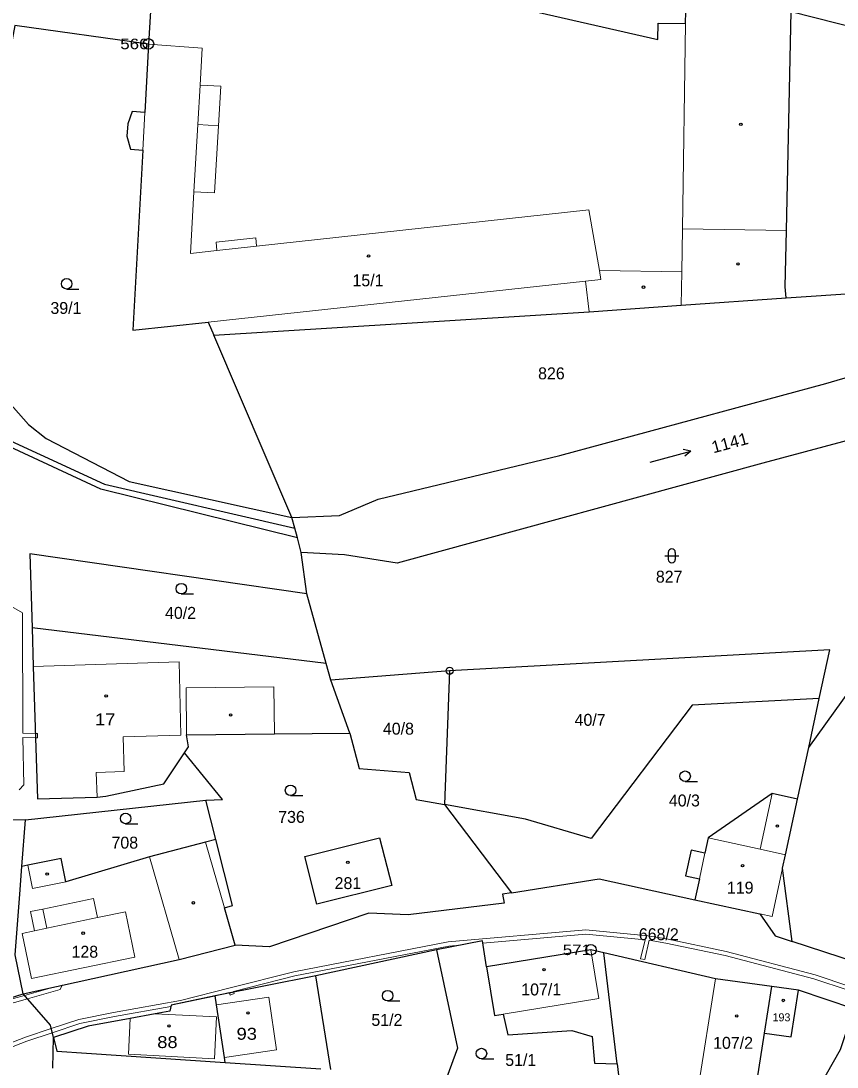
# Model space of a CAD drawing. Extents: x -758887 to -754328, y -1031688 to -1029144.
# Drawn here: x -756296.2 to -756179.9, y -1030447.4 to -1030298.3 of the extents above; entities that cross this region are included whole.
import ezdxf
from ezdxf.enums import TextEntityAlignment as Align

# ---------------------------------------------------------------- set-up
doc = ezdxf.new("R2010")
doc.units = 0
doc.header["$LTSCALE"] = 0.68
for name, color, linetype, lineweight in [('1', 7, 'Continuous', 25), ('13', 7, 'Continuous', 13), ('3', 7, 'Continuous', 25), ('4', 7, 'Continuous', 13), ('5', 7, 'Continuous', 25), ('8', 7, 'Continuous', 25)]:
    doc.layers.add(name, color=color, linetype=linetype, lineweight=lineweight)
doc.layers.add('2', color=7, linetype='Continuous')

msp = doc.modelspace()

# ---------------------------------------------------------------- linework, layer by layer
at = {"layer": '1'}
for p, q in [((-756186.43, -1030296.97), (-756172.86, -1030300.43)), ((-756187.15, -1030337.79), (-756168.3, -1030336.57)), ((-756256.83, -1030371.98), (-756257.2, -1030370.6)), ((-756252.73, -1030389.88), (-756255.47, -1030379.95)), ((-756252.73, -1030389.88), (-756294.64, -1030384.82)), ((-756252.07, -1030392.26), (-756252.73, -1030389.88)), ((-756235.12, -1030390.94), (-756252.07, -1030392.26)), ((-756249.36, -1030399.82), (-756252.07, -1030392.26)), ((-756295.58, -1030412.18), (-756269.89, -1030409.39)), ((-756268.47, -1030415), (-756269.89, -1030409.39)), ((-756235.85, -1030410), (-756226.28, -1030422.56)), ((-756177.1, -1030432.5), (-756186.27, -1030429.51)), ((-756254.19, -1030434.42), (-756268.53, -1030437.28)), ((-756252.05, -1030447.75), (-756254.19, -1030434.42)), ((-756190.23, -1030442.57), (-756189.18, -1030435.94)), ((-756185.37, -1030436.47), (-756189.18, -1030435.94)), ((-756177.49, -1030439.12), (-756185.37, -1030436.47)), ((-756268.53, -1030437.28), (-756274.82, -1030438.59)), ((-756191.78, -1030452.34), (-756190.23, -1030442.57)), ((-756291.68, -1030447.55), (-756291.6, -1030443.2)), ((-756211.22, -1030446.93), (-756210.83, -1030450.16))]:
    msp.add_line(p, q, dxfattribs=at)
for points in [[(-756277.43, -1030291.05), (-756277.68, -1030295.34), (-756278.04, -1030301.63)], [(-756277.43, -1030291.05), (-756267.6, -1030291.62), (-756262.8, -1030291.89), (-756257.46, -1030292.14), (-756257.5, -1030292.9), (-756254.89, -1030293.02), (-756248.59, -1030293.81), (-756241.94, -1030294.65), (-756222.37, -1030297.12), (-756205.42, -1030300.96), (-756205.39, -1030298.66), (-756201.49, -1030298.72), (-756201.46, -1030296.97), (-756186.43, -1030296.97)], [(-756187.15, -1030337.79), (-756187.28, -1030336.24), (-756187.11, -1030328.19), (-756186.43, -1030296.97)], [(-756278.04, -1030301.63), (-756297.11, -1030298.97), (-756305.25, -1030342.25), (-756301.61, -1030348.57), (-756295.16, -1030355.83), (-756292.62, -1030357.83), (-756280.82, -1030363.98), (-756257.6, -1030369.08), (-756268.75, -1030343.09)], [(-756278.04, -1030301.63), (-756278.58, -1030311.36), (-756280.37, -1030311.26), (-756281.01, -1030312.99), (-756281.13, -1030314.74), (-756280.62, -1030316.63), (-756278.88, -1030316.76), (-756280.3, -1030342.42), (-756269.52, -1030341.25), (-756268.75, -1030343.09)], [(-756256.83, -1030371.98), (-756284.83, -1030365.07), (-756303.39, -1030356.44), (-756320.2, -1030338.64), (-756353.07, -1030315.54), (-756371.23, -1030308.81), (-756412.68, -1030321.55), (-756420.88, -1030328.31), (-756431.02, -1030341.76)], [(-756383.9, -1030311.42), (-756371.64, -1030307.47), (-756352.7, -1030314.7), (-756319.28, -1030338.35), (-756302.7, -1030355.9), (-756284.33, -1030364.33), (-756257.2, -1030370.6), (-756257.6, -1030369.08)], [(-756268.75, -1030343.09), (-756215.21, -1030339.78), (-756202.09, -1030338.85), (-756187.15, -1030337.79)], [(-756257.6, -1030369.08), (-756250.83, -1030368.82), (-756245.31, -1030366.48), (-756219.4, -1030360.24), (-756181.47, -1030350.02), (-756152, -1030341.34)], [(-756183.93, -1030401.88), (-756175.52, -1030390.23), (-756148.24, -1030383.26), (-756132.67, -1030381.9), (-756135.32, -1030348.08)], [(-756149.65, -1030350.41), (-756190.47, -1030361.36), (-756242.58, -1030375.6), (-756250.11, -1030374.41), (-756256.28, -1030374.07)], [(-756255.47, -1030379.95), (-756256.28, -1030374.07), (-756256.83, -1030371.98)], [(-756255.47, -1030379.95), (-756294.98, -1030374.28), (-756294.64, -1030384.82)], [(-756294.64, -1030384.82), (-756294.47, -1030390.32), (-756293.86, -1030409.21), (-756285.38, -1030408.94), (-756284.13, -1030408.82), (-756275.87, -1030407.03), (-756272.9, -1030402.61)], [(-756182.41, -1030394.87), (-756180.9, -1030387.93), (-756235.12, -1030390.94), (-756235.85, -1030410)], [(-756182.41, -1030394.87), (-756200.53, -1030395.85), (-756214.93, -1030414.83), (-756224.29, -1030412.09), (-756235.85, -1030410)], [(-756185.52, -1030409.24), (-756183.93, -1030401.88), (-756182.41, -1030394.87)], [(-756272.9, -1030402.61), (-756272.34, -1030401.77), (-756272.61, -1030400.07), (-756260.1, -1030399.94), (-756249.36, -1030399.82)], [(-756249.36, -1030399.82), (-756248, -1030404.88), (-756240.87, -1030405.45), (-756239.88, -1030409.27), (-756235.85, -1030410)], [(-756269.89, -1030409.39), (-756267.52, -1030409.29), (-756272.9, -1030402.61)], [(-756185.52, -1030409.24), (-756189.14, -1030408.45), (-756198.25, -1030414.76), (-756198.72, -1030416.91), (-756200.67, -1030416.49), (-756201.47, -1030420.15), (-756199.51, -1030420.58), (-756200.16, -1030423.56)], [(-756186.27, -1030429.51), (-756187.66, -1030419.07), (-756187.24, -1030417.15), (-756185.52, -1030409.24)], [(-756295.58, -1030412.18), (-756299.87, -1030412.23), (-756303.37, -1030412.27), (-756318.47, -1030412.45), (-756318.97, -1030412.78), (-756320.79, -1030424.85), (-756321.31, -1030429.38), (-756321.97, -1030435.17)], [(-756295.92, -1030436.99), (-756297.06, -1030431.43), (-756296.39, -1030422.75), (-756296.09, -1030418.82), (-756295.58, -1030412.18)], [(-756268.47, -1030415), (-756269.92, -1030415.37), (-756277.9, -1030417.43), (-756289.83, -1030421), (-756290.52, -1030417.67), (-756295.27, -1030418.65), (-756296.09, -1030418.82)], [(-756265.7, -1030430.04), (-756267.22, -1030424.74), (-756266.07, -1030424.41), (-756268.47, -1030415)], [(-756226.28, -1030422.56), (-756213.8, -1030420.6), (-756200.16, -1030423.56)], [(-756226.28, -1030422.56), (-756227.56, -1030422.76), (-756227.36, -1030424.06), (-756241.01, -1030425.72), (-756246.65, -1030425.46), (-756260.81, -1030430.27), (-756265.7, -1030430.04)], [(-756200.16, -1030423.56), (-756190.91, -1030425.57), (-756188.71, -1030428.71), (-756186.27, -1030429.51)], [(-756229.84, -1030433.11), (-756230.44, -1030429.4), (-756236.98, -1030430.71), (-756254.19, -1030434.42)], [(-756295.92, -1030436.99), (-756273.68, -1030432.1), (-756265.7, -1030430.04)], [(-756236.98, -1030430.71), (-756234.01, -1030444.73), (-756235.5, -1030448.86)], [(-756213.11, -1030431.14), (-756214.98, -1030430.7), (-756229.84, -1030433.11)], [(-756229.84, -1030433.11), (-756228.72, -1030440.05), (-756227.49, -1030439.85), (-756226.81, -1030442.84), (-756217.68, -1030442.21), (-756214.8, -1030443.06), (-756214.48, -1030446.85), (-756211.22, -1030446.93), (-756213.11, -1030431.14)], [(-756189.18, -1030435.94), (-756197.21, -1030434.84), (-756213.11, -1030431.14)], [(-756307.55, -1030441.95), (-756301.06, -1030438.61), (-756295.92, -1030436.99)], [(-756291.6, -1030443.2), (-756292.02, -1030441.45), (-756295.92, -1030436.99)], [(-756190.23, -1030442.57), (-756186.42, -1030443.1), (-756185.37, -1030436.47)], [(-756274.82, -1030438.59), (-756275.01, -1030439.46), (-756277.11, -1030439.84), (-756280.68, -1030440.49), (-756286.64, -1030441.58), (-756291.6, -1030443.2)], [(-756267.13, -1030446.74), (-756267.23, -1030446.07), (-756268.34, -1030438.55), (-756268.53, -1030437.28)], [(-756177.49, -1030439.12), (-756179.45, -1030444.96), (-756182.43, -1030450.22), (-756185.07, -1030453.38), (-756190.89, -1030458.98), (-756194.45, -1030461.45)], [(-756291.6, -1030443.2), (-756291.13, -1030445.14), (-756286.88, -1030445.42), (-756267.13, -1030446.74), (-756253.5, -1030447.65)]]:
    msp.add_lwpolyline(points, dxfattribs=at)
msp.add_lwpolyline([(-756254.05, -1030424.2), (-756255.76, -1030417.41), (-756245.1, -1030414.74), (-756243.38, -1030421.53)], close=True, dxfattribs=at)
at = {"layer": '13'}
for points in [[(-756296.5, -1030407.91), (-756295.84, -1030407.17), (-756295.96, -1030400.44), (-756294.14, -1030400.48), (-756294.16, -1030399.87), (-756295.97, -1030399.84), (-756296.01, -1030382.66), (-756303.59, -1030378.37)], [(-756178.08, -1030435.91), (-756183.01, -1030434.25), (-756195.68, -1030430.94), (-756204.18, -1030429.16), (-756206.86, -1030428.7), (-756215.7, -1030427.87), (-756235.32, -1030429.58), (-756257.35, -1030433.83), (-756266.4, -1030436.12), (-756273.48, -1030437.91), (-756283.02, -1030439.64), (-756287.98, -1030440.64), (-756291.91, -1030441.93), (-756295.6, -1030443.14), (-756305.75, -1030447.1), (-756309.59, -1030448.39)], [(-756305.55, -1030447.66), (-756295.4, -1030443.7), (-756291.77, -1030442.51), (-756287.82, -1030441.22), (-756282.9, -1030440.22), (-756274.86, -1030438.77), (-756274.82, -1030438.59), (-756268.65, -1030437.3), (-756266.53, -1030436.77), (-756266.49, -1030436.87), (-756265.9, -1030436.76), (-756265.95, -1030436.62), (-756257.21, -1030434.41), (-756235.24, -1030430.18), (-756233.61, -1030430.04), (-756230.44, -1030429.4), (-756230.38, -1030429.75), (-756215.7, -1030428.47), (-756207.26, -1030429.27), (-756207.89, -1030431.97), (-756207.31, -1030432.1), (-756206.66, -1030429.34), (-756204.3, -1030429.74), (-756195.82, -1030431.52), (-756183.19, -1030434.83), (-756178.28, -1030436.47)], [(-756298.99, -1030438.74), (-756295.3, -1030437.7), (-756290.64, -1030436.38), (-756290.34, -1030435.76), (-756291.76, -1030436.07), (-756295.74, -1030437.2), (-756299.19, -1030438.18)]]:
    msp.add_lwpolyline(points, dxfattribs=at)
for points in [[(-756294.16, -1030399.87), (-756294.14, -1030400.48), (-756293.89, -1030400.48), (-756293.89, -1030399.88)], [(-756265.9, -1030436.76), (-756266.49, -1030436.87), (-756266.41, -1030437.15), (-756265.84, -1030436.94)]]:
    msp.add_lwpolyline(points, close=True, dxfattribs=at)
at = {"layer": '3'}
for p, q in [((-756289.713, -1030336.54), (-756287.963, -1030336.54)), ((-756200.753, -1030359.637), (-756201.568, -1030360.375)), ((-756203.941, -1030374.061), (-756203.941, -1030375.062)), ((-756202.939, -1030375.062), (-756202.939, -1030374.061)), ((-756204.441, -1030374.561), (-756202.439, -1030374.561)), ((-756273.373, -1030379.99), (-756271.623, -1030379.99)), ((-756201.543, -1030406.72), (-756199.793, -1030406.72)), ((-756257.803, -1030408.72), (-756256.053, -1030408.72)), ((-756281.313, -1030412.73), (-756279.563, -1030412.73)), ((-756243.953, -1030437.99), (-756242.203, -1030437.99)), ((-756230.583, -1030446.24), (-756228.833, -1030446.24))]:
    msp.add_line(p, q, dxfattribs=at)
msp.add_lwpolyline([(-756206.549, -1030361.19), (-756200.753, -1030359.637), (-756201.827, -1030359.406)], dxfattribs=at)
for centre in [(-756289.7129, -1030335.7898), (-756273.3729, -1030379.2398), (-756201.5429, -1030405.9698), (-756257.8029, -1030407.9698), (-756281.3129, -1030411.9798), (-756243.9529, -1030437.2398), (-756230.5829, -1030445.4898)]:
    msp.add_circle(centre, 0.75, dxfattribs=at)
for centre, start, end in [((-756203.44, -1030374.0609), 0, 180), ((-756203.44, -1030375.0609), 180, 359.98789)]:
    msp.add_arc(centre, 0.5, start, end, dxfattribs=at)
at = {"layer": '4'}
for p, q in [((-756201.93, -1030327.97), (-756201.49, -1030298.72)), ((-756278.04, -1030301.63), (-756270.4, -1030302.23)), ((-756270.7, -1030307.47), (-756271.02, -1030313.11)), ((-756267.75, -1030307.64), (-756268.08, -1030313.28)), ((-756278.88, -1030316.76), (-756278.58, -1030311.36)), ((-756271.02, -1030313.11), (-756271.57, -1030322.68)), ((-756268.08, -1030313.28), (-756271.02, -1030313.11)), ((-756268.08, -1030313.28), (-756268.62, -1030322.85)), ((-756272.07, -1030331.47), (-756271.57, -1030322.68)), ((-756268.62, -1030322.85), (-756271.57, -1030322.68)), ((-756262.63, -1030330.43), (-756215.28, -1030325.25)), ((-756215.28, -1030325.25), (-756213.77, -1030333.92)), ((-756201.93, -1030327.97), (-756202.02, -1030334.11)), ((-756201.93, -1030327.97), (-756187.11, -1030328.19)), ((-756262.76, -1030329.24), (-756268.42, -1030329.86)), ((-756262.63, -1030330.43), (-756262.76, -1030329.24)), ((-756272.07, -1030331.47), (-756268.29, -1030331.06)), ((-756268.42, -1030329.86), (-756268.29, -1030331.06)), ((-756268.29, -1030331.06), (-756262.63, -1030330.43)), ((-756213.77, -1030333.92), (-756213.55, -1030335.18)), ((-756213.77, -1030333.92), (-756202.02, -1030334.11)), ((-756202.02, -1030334.11), (-756202.09, -1030338.85)), ((-756215.74, -1030335.42), (-756269.52, -1030341.25)), ((-756213.55, -1030335.18), (-756215.74, -1030335.42)), ((-756215.21, -1030339.78), (-756215.74, -1030335.42)), ((-756273.68, -1030389.65), (-756294.47, -1030390.32)), ((-756273.68, -1030389.65), (-756273.46, -1030400.1)), ((-756272.68, -1030393.37), (-756272.61, -1030400.07)), ((-756273.46, -1030400.1), (-756281.65, -1030400.36)), ((-756281.65, -1030400.36), (-756281.5, -1030405.31)), ((-756281.5, -1030405.31), (-756285.49, -1030405.44)), ((-756285.49, -1030405.44), (-756285.38, -1030408.94)), ((-756269.92, -1030415.37), (-756267.22, -1030424.74)), ((-756273.68, -1030432.1), (-756277.9, -1030417.43)), ((-756198.72, -1030416.91), (-756199.51, -1030420.58)), ((-756190.86, -1030416.37), (-756187.24, -1030417.15)), ((-756295.27, -1030418.65), (-756294.58, -1030421.98)), ((-756187.66, -1030419.07), (-756189.15, -1030425.95)), ((-756294.58, -1030421.98), (-756289.83, -1030421)), ((-756293.11, -1030424.89), (-756285.87, -1030423.4)), ((-756285.31, -1030426.09), (-756285.87, -1030423.4)), ((-756294.88, -1030425.26), (-756294.31, -1030428)), ((-756292.55, -1030427.64), (-756285.31, -1030426.09)), ((-756281.35, -1030425.27), (-756285.31, -1030426.09)), ((-756280.02, -1030431.74), (-756281.35, -1030425.27)), ((-756190.91, -1030425.57), (-756189.15, -1030425.95)), ((-756294.31, -1030428), (-756296.07, -1030428.36)), ((-756294.31, -1030428), (-756292.55, -1030427.64)), ((-756296.07, -1030428.36), (-756294.75, -1030434.78)), ((-756214.98, -1030430.7), (-756213.85, -1030437.64)), ((-756294.75, -1030434.78), (-756280.02, -1030431.74)), ((-756199.73, -1030450.74), (-756197.21, -1030434.84)), ((-756268.34, -1030438.55), (-756260.89, -1030437.45)), ((-756259.78, -1030444.97), (-756260.89, -1030437.45)), ((-756227.49, -1030439.85), (-756213.85, -1030437.64)), ((-756268.35, -1030440.23), (-756277.11, -1030439.84)), ((-756280.68, -1030440.49), (-756280.92, -1030445.56)), ((-756268.64, -1030446.22), (-756268.35, -1030440.23)), ((-756280.92, -1030445.56), (-756268.64, -1030446.22)), ((-756267.23, -1030446.07), (-756259.78, -1030444.97))]:
    msp.add_line(p, q, dxfattribs=at)
for points in [[(-756270.4, -1030302.23), (-756270.7, -1030307.47), (-756267.75, -1030307.64)], [(-756272.68, -1030393.37), (-756260.17, -1030393.24), (-756260.1, -1030399.94)], [(-756198.25, -1030414.76), (-756190.86, -1030416.37), (-756189.14, -1030408.45)], [(-756292.55, -1030427.64), (-756293.11, -1030424.89), (-756294.88, -1030425.26)]]:
    msp.add_lwpolyline(points, dxfattribs=at)
at = {"layer": '5'}
for centre in [(-756193.5968, -1030313.0592), (-756246.6768, -1030331.8192), (-756194.0168, -1030332.9692), (-756207.4768, -1030336.2692), (-756284.0868, -1030394.5292), (-756266.3468, -1030397.2292), (-756188.3968, -1030413.0592), (-756249.6268, -1030418.2392), (-756193.3568, -1030418.6992), (-756292.4968, -1030419.8992), (-756271.6568, -1030424.0092), (-756287.3668, -1030428.3292), (-756221.6568, -1030433.5192), (-756187.5468, -1030437.9192), (-756263.8768, -1030439.6992), (-756194.1868, -1030440.1292), (-756275.1368, -1030441.5492)]:
    msp.add_circle(centre, 0.175, dxfattribs=at)
at = {"layer": '8'}
for centre, radius in [((-756278.06, -1030301.6098), 0.75), ((-756278.06, -1030301.6098), 0.03), ((-756235.12, -1030390.9399), 0.5), ((-756235.12, -1030390.9399), 0.0303), ((-756214.97, -1030430.6998), 0.75), ((-756214.97, -1030430.6998), 0.03)]:
    msp.add_circle(centre, radius, dxfattribs=at)

# ---------------------------------------------------------------- texts
at = {"layer": '2'}
for s, height, p in [('15/1', 1.7, (-756246.76, -1030336.15)), ('39/1', 1.7, (-756289.82, -1030340.09)), ('826', 1.7, (-756220.609, -1030349.406)), ('827', 1.7, (-756203.819, -1030378.376)), ('40/2', 1.7, (-756273.48, -1030383.54)), ('40/8', 1.7, (-756242.42, -1030400.04)), ('40/7', 1.7, (-756215.09, -1030398.78)), ('40/3', 1.7, (-756201.65, -1030410.27)), ('736', 1.7, (-756257.659, -1030412.61)), ('708', 1.7, (-756281.429, -1030416.28)), ('281', 1.7, (-756249.619, -1030422.05)), ('119', 1.7, (-756193.689, -1030422.69)), ('668/2', 1.7, (-756205.3, -1030429.33)), ('128', 1.7, (-756287.129, -1030431.83)), ('107/1', 1.7, (-756222.06, -1030437.2)), ('51/2', 1.7, (-756244.06, -1030441.54)), ('193', 1.14, (-756187.81, -1030440.89)), ('107/2', 1.7, (-756194.71, -1030444.81)), ('51/1', 1.7, (-756224.98, -1030447.25))]:
    msp.add_text(s, height=height, dxfattribs=at).set_placement(p, align=Align.CENTER)
at = {"layer": '2', "width": 1.05}
msp.add_text('1141', height=1.7, rotation=15, dxfattribs=at).set_placement((-756194.957, -1030359.2689), align=Align.CENTER)
at = {"layer": '2', "width": 1.15}
for s, p in [('17', (-756284.22, -1030398.72)), ('88', (-756275.35, -1030444.7)), ('93', (-756264.04, -1030443.52))]:
    msp.add_text(s, height=1.7, dxfattribs=at).set_placement(p, align=Align.CENTER)
at = {"layer": '8', "width": 1.2}
for s, p in [('566', (-756278.06, -1030302.36)), ('571', (-756214.97, -1030431.45))]:
    msp.add_text(s, height=1.5, dxfattribs=at).set_placement(p, align=Align.RIGHT)

doc.saveas('drawing.dxf')
